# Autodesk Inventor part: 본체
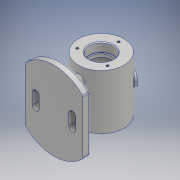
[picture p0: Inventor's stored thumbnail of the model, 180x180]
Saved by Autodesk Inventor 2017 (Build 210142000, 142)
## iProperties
Part Number: 본체
Material: 알루미늄 6061
Document SubType Name: Modeling
Designer: 601-19
Density: 2.7 g/cm^3
Appearance: 알루미늄 - 평지
Mass: 496.239 g
Surface Area: 492.781 cm^2
Volume: 183.792 cm^3
Author: 601-19
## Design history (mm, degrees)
sketch "스케치1"
  geometry: L1 (38, 35.496)-(38, -35.496); L2 (-38, -35.496)-(-38, 35.496); C1 r 52 at (0, 0); A1 r 52 centre (0, 0) between (38, 35.496) and (-38, 35.496); A2 r 52 centre (0, 0) between (-38, -35.496) and (38, -35.496); 4 further points
  constraints: 4 end point, 4 point on circle, 3 centre point, 2 coincident, 2 horizontal alignment, 2 midpoint, 1 concentric, 1 parallel, 1 vertical alignment
  dimensions: "d2" = 52 radius of A1; "d3" = 52 radius of A2; "d4" = 76 distance between parallel lines of L2 L1; "d5" = 70.99296 distance of L1.start L1.end
extrude "돌출1" new body sketch "스케치1" distance "d6" = 10; taper "d7" = 0 deg
sketch "스케치2"
  geometry: L1 (78, 36)-(92, 36); L2 (92, 36)-(92, -36); L3 (62, 20)-(87, 20); L4 (87, -20)-(62, -20); L5 (62, 24)-(76, 24); L6 (76, 24)-(76, 20); L7 (76, 20)-(62, 20); L8 (78, 36)-(78, 24); L9 (62, -20)-(74.5, -20); L10 (74.5, -20)-(74.5, -24); L11 (74.5, -24)-(62, -24); L12 (78, -36)-(78, -24); L13 (62, 36)-(62, -52.194); L14 (0, -35.496)-(0, -52) reference; L15 (87, 20)-(87, -20); L16 (78, 24)-(62, 24); L17 (78, -24)-(62, -24); L18 (92, -36)-(78, -36); L19 (10, 35.496)-(10, -35.496) reference; 5 further points
  constraints: 34 end point, 6 vertical alignment, 5 horizontal, 4 point on line, 3 midpoint, 3 parallel, 3 perpendicular, 2 horizontal alignment, 1 vertical
  dimensions: "d19" = 62 distance from line of L14 L13.end; "d20" = 72 distance of L1.end L2.end; "d21" = 40 distance of L3.end L4.start; "d22" = 32 diameter of L12.start L13; "d23" = 25 diameter of L10 L13; "d24" = 60 diameter of L2 L13; "d25" = 12 distance of L12.start L12.end; "d26" = 12 distance of L1.start L8.end
revolve "회전1" sketch "스케치2" stored, may be unused: angle "d27" = 90 deg
fillet "모깎기1" dims "d28" = 3
chamfer "모따기1" distance "d29" = 1; stored, may be unused: second distance "d30" = 2, angle "d31" = 45 deg
sketch "스케치3"
  geometry: L1 (-7, -19)-(-7, 19); L2 (7, 19)-(7, -19); L3 (7, -19)-(-7, 19); L4 (-7, -19)-(7, 19); L5 (-28.5, -7.5)-(-28.5, 7.5); L6 (-19.5, 7.5)-(-19.5, -7.5); L7 (-21.882, -3.529)-(-28.5, 7.5); L8 (-28.5, -7.5)-(-19.5, 7.5); L9 (19.5, -7.5)-(19.5, 7.5); L10 (28.5, 7.5)-(28.5, -7.5); L11 (28.5, -7.5)-(19.5, 7.5); L12 (19.5, -7.5)-(28.5, 7.5); A1 r 7 centre (0, 19) between (7, 19) and (-7, 19); A2 r 7 centre (0, -19) between (-7, -19) and (7, -19); A3 r 4.5 centre (24, 7.5) between (28.5, 7.5) and (19.5, 7.5); A4 r 4.5 centre (24, -7.5) between (19.5, -7.5) and (28.5, -7.5); A5 r 4.5 centre (-24, 7.5) between (-19.5, 7.5) and (-28.5, 7.5); A6 r 4.5 centre (-24, -7.5) between (-28.5, -7.5) and (-19.5, -7.5); 11 further points
  constraints: 24 end point, 12 midpoint, 12 point on circle, 6 centre point, 5 horizontal alignment, 3 parallel, 2 point on line
  dimensions: "d32" = 14 distance of L1.end L2.start; "d34" = 9 distance of L5.end L6.start; "d35" = 14 distance of L2.end L1.start; "d36" = 7 radius of A2; "d37" = 38 distance of L1.start L1.end; "d39" = 24 distance of point (0, 0) point (-24, 0); "d40" = 24 distance of point (24, 0) point (0, 0); "d41" = 9 distance of L10.start L9.end; "d42" = 15 distance of L5.end L5.start; "d43" = 15 distance of L9.start L9.end
extrude "돌출2" cut sketch "스케치3" distance "d44" = 10; taper "d45" = 0 deg
extrude "돌출3" join sketch "스케치3" distance "d46" = 27; taper "d47" = 0 deg
sketch "스케치4"
  geometry: L1 (12.935, 84.404)-(19.863, 80.404); L2 (23.428, 86.579)-(16.5, 90.579); L3 (19.863, 80.404)-(23.428, 86.579); L4 (12.935, 84.404)-(16.5, 90.579); C1 r 12.5 at (0, 62) reference; 1 further point
  constraints: 8 end point, 1 parallel, 1 perpendicular
revolve "회전2" sketch "스케치4" stored, may be unused: angle "d54" = 90 deg
sketch "스케치5"
  geometry: C1 r 8 at (0, 0) reference; 1 further point
hole "구멍1" sketch "스케치5" at (0, 0) diameter "d55" = 8; stored, may be unused: countersink angle "d59" = 90 deg, drill point angle "d61" = 118 deg; dims "d56" = 6, "d57" = 4, "d58" = 2, "d60" = 12.5
fillet "모깎기2" dims "d62" = 1
fillet "모깎기3" dims "d66" = 3
fillet "모깎기4" dims "d67" = 3
fillet "모깎기5" dims "d68" = 0.3
fillet "모깎기6" dims "d69" = 1
sketch "스케치6" dims "d70" = 46
  geometry: C1 r 14 at (0, 0) reference; 5 further points
  constraints: 1 coincident, 1 vertical alignment, 6 other
  dimensions: "d73" = 360 deg dimension on point (0, 0) point (0, 23) (derived)
hole "구멍2" sketch "스케치6" at (0, 23), (-19.919, -11.5), (19.919, -11.5) diameter "d75" = 3.242; stored, may be unused: countersink angle "d79" = 90 deg, drill point angle "d81" = 118 deg; dims "d76" = 8, "d77" = 4, "d78" = 2, "d80" = 10
sketch "스케치7"
  geometry: C1 r 42.5 at (0, 0); 1 further point
  constraints: 1 centre point, 1 coincident, 1 other
  dimensions: "d82" = 85 diameter of C1
extrude "돌출4" join sketch "스케치7" distance "d83" = 0.5; taper "d84" = 0 deg
node "솔리드1"
mirror "미러1"
other parameters: "d0" = 104, "d50" = 30 deg, "d51" = 90 deg, "d52" = 33, "d53" = 8
